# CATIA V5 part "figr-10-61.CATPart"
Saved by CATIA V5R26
Part number: Part3
Bounding box of the stored display mesh (mm): x -76.186 to 89.68, y -206 to 106, z -21.666 to 136.547
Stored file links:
  D:\_Deepak\CATIA\CATIA V5-6R2016_Deepak\Resources\Part files\Partfiles\c10_catia_v5_6r2016_prt\figr-10-61.CATPart
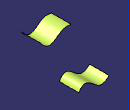
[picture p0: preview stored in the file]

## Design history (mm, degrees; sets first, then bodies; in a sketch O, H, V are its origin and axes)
Set1
  Plane1: type Offset, RefPlane zx-plane, Offset 100, reversed
  Sketch1 on Plane1, origin (0, -100, 0), H (-1, 0, 0), V (0, 0, 1)
    spline S1 through (-89.6797, 128.7958) (-21.8257, 98.6681) (14.6145, 123.4397) (76.1857, 133.4823)
  Extrude1: Element1 Sketch2, Lim1 106, Lim2 0, Direction zx-plane
  Extrude2: Element1 Sketch1, Lim1 106, Lim2 0, Direction Plane1
Body1 (main body)
  Sketch2 on zx-plane, origin (0, 0, 0), H (-1, 0, 0), V (0, 0, 1)
    spline S1 through (-88.2413, 0) (-57.9275, 26.3209) (-11.5211, 3.1904) (32.6399, -21.5353) (74.1811, 0)
    point P1 (-88.2413, 0)
    point P2 (74.1811, 0)
    coincidence: P1 H, P2 H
